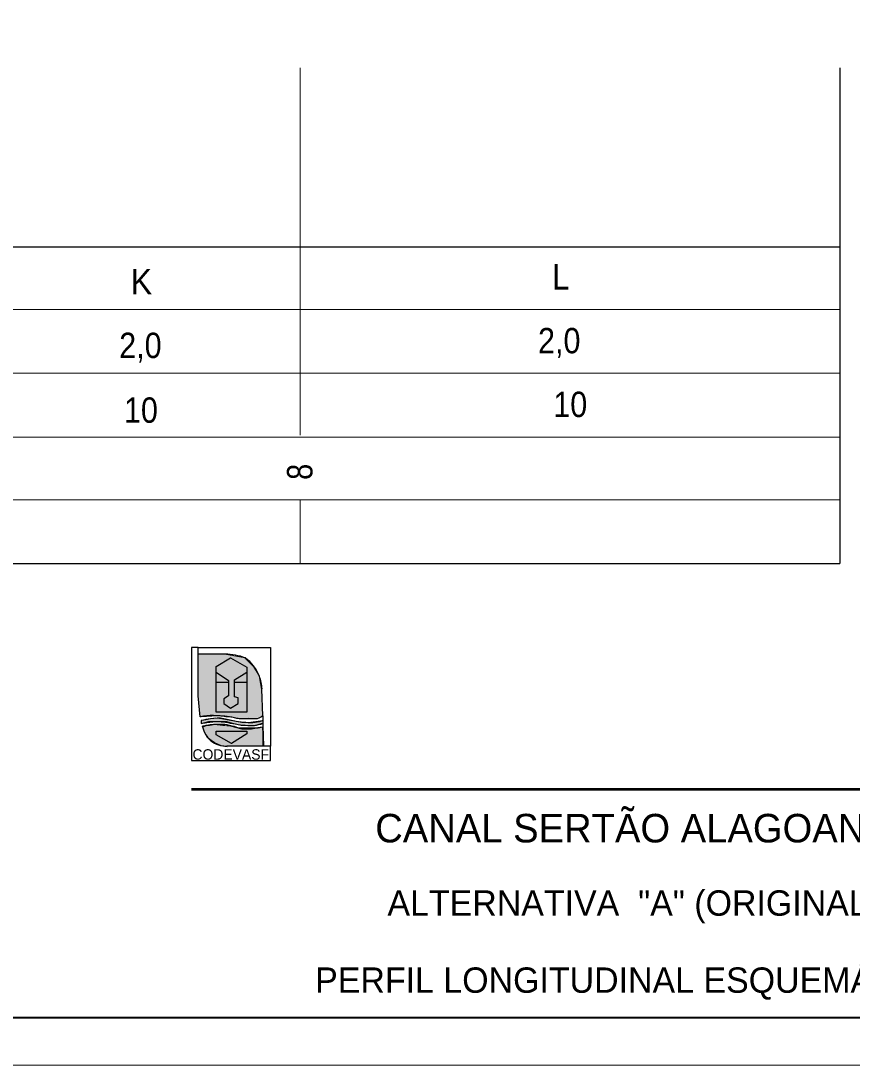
# Model space of a CAD drawing. Extents: x 8426.2 to 8495.4, y 19933.5 to 19963.2.
# Drawn here: x 8482.15 to 8490.88, y 19933.55 to 19944.52 of the extents above; entities that cross this region are included whole.
import ezdxf
from ezdxf.enums import TextEntityAlignment as Align

# ---------------------------------------------------------------- set-up
doc = ezdxf.new("R2010")
doc.units = 0
doc.header["$LTSCALE"] = 0.11
for name, color, linetype, lineweight in [('1', 7, 'Continuous', 35), ('3', 7, 'Continuous', 25), ('8', 7, 'Continuous', 13)]:
    doc.layers.add(name, color=color, linetype=linetype, lineweight=lineweight)

msp = doc.modelspace()

# ---------------------------------------------------------------- hatches: boundary and pattern name
at = {"layer": '8'}
for points in [[(8484.01, 19937.87), (8484.29, 19937.87), (8484.5, 19937.83), (8484.59, 19937.74), (8484.65, 19937.64), (8484.68, 19937.5), (8484.69, 19937.22), (8484.63, 19937.19), (8484.48, 19937.19), (8484.33, 19937.21), (8484.21, 19937.22), (8484.04, 19937.21), (8484.03, 19937.21), (8484.01, 19937.43), (8484.01, 19937.65)], [(8484.04, 19937.17), (8484.04, 19937.14), (8484.12, 19937.16), (8484.26, 19937.16), (8484.31, 19937.16), (8484.42, 19937.13), (8484.52, 19937.12), (8484.6, 19937.12), (8484.69, 19937.14), (8484.69, 19937.17), (8484.54, 19937.15), (8484.47, 19937.15), (8484.26, 19937.19), (8484.19, 19937.2)], [(8484.69, 19936.9), (8484.31, 19936.9), (8484.25, 19936.91), (8484.18, 19936.94), (8484.11, 19936.99), (8484.07, 19937.06), (8484.06, 19937.1), (8484.1, 19937.12), (8484.18, 19937.13), (8484.27, 19937.12), (8484.35, 19937.11), (8484.47, 19937.08), (8484.57, 19937.08), (8484.67, 19937.1), (8484.69, 19937.1)], [(8484.2, 19937.06), (8484.2, 19937.02), (8484.36, 19936.93), (8484.52, 19937.03), (8484.52, 19937.06)]]:
    msp.add_hatch(color=256, dxfattribs=at).paths.add_polyline_path(points)

# ---------------------------------------------------------------- linework, layer by layer
at = {"layer": '1', "lineweight": 53}
msp.add_line((8483.94, 19936.45), (8493.94, 19936.45), dxfattribs=at)
at = {"layer": '1', "lineweight": 13}
msp.add_lwpolyline([(8426.17, 19933.55), (8495.44, 19933.55), (8495.44, 19963.25), (8426.17, 19963.25)], close=True, dxfattribs=at)
at = {"layer": '1', "lineweight": 40}
msp.add_lwpolyline([(8428.67, 19934.05), (8494.94, 19934.05), (8494.94, 19962.75)], dxfattribs=at)
at = {"layer": '3', "lineweight": 13}
for p, q in [((8485.08, 19944.03), (8485.08, 19940.17)), ((8432.23, 19941.49), (8490.75, 19941.49)), ((8432.23, 19940.82), (8490.75, 19940.82)), ((8432.23, 19940.15), (8490.75, 19940.15)), ((8433.47, 19940.15), (8490.75, 19940.15)), ((8432.23, 19939.49), (8490.75, 19939.49)), ((8485.08, 19939.49), (8485.08, 19938.82))]:
    msp.add_line(p, q, dxfattribs=at)
at = {"layer": '3'}
for p, q in [((8490.75, 19944.03), (8490.75, 19938.82)), ((8432.23, 19942.15), (8490.75, 19942.15)), ((8432.23, 19938.82), (8490.75, 19938.82)), ((8484.01, 19937.87), (8484.01, 19937.94)), ((8484.29, 19937.87), (8484.01, 19937.87)), ((8484.2, 19937.26), (8484.2, 19937.74)), ((8484.33, 19937.57), (8484.2, 19937.57)), ((8484.52, 19937.57), (8484.39, 19937.57)), ((8484.69, 19937.22), (8484.68, 19937.5)), ((8484.7, 19936.9), (8484.69, 19937.1)), ((8484.77, 19936.9), (8484.31, 19936.9))]:
    msp.add_line(p, q, dxfattribs=at)
for points in [[(8484.01, 19937.94), (8483.94, 19937.94), (8483.94, 19936.75), (8484.77, 19936.75), (8484.77, 19936.9)], [(8484.01, 19937.94), (8484.77, 19937.94), (8484.77, 19936.9)], [(8484.03, 19937.21), (8484.01, 19937.43), (8484.01, 19937.87)], [(8484.2, 19937.74), (8484.35, 19937.83), (8484.52, 19937.73)], [(8484.52, 19937.73), (8484.52, 19937.26), (8484.2, 19937.26)], [(8484.2, 19937.68), (8484.33, 19937.59), (8484.33, 19937.43), (8484.28, 19937.4), (8484.28, 19937.35), (8484.35, 19937.3), (8484.43, 19937.35), (8484.43, 19937.41), (8484.39, 19937.42), (8484.39, 19937.6), (8484.52, 19937.68)]]:
    msp.add_lwpolyline(points, dxfattribs=at)
msp.add_lwpolyline([(8484.2, 19937.06), (8484.52, 19937.06), (8484.52, 19937.03), (8484.36, 19936.93), (8484.2, 19937.02)], close=True, dxfattribs=at)
msp.add_lwpolyline([(8484.2, 19937.06), (8484.52, 19937.06), (8484.52, 19937.03), (8484.36, 19936.93), (8484.2, 19937.02)], close=True, dxfattribs=at)
for centre, radius, start, end in [((8484.284, 19937.219), 0.649, 70.2011, 89.1197), ((8484.261, 19937.485), 0.421, 21.2511, 54.7896), ((8483.978, 19937.422), 0.709, 6.5558, 17.6915), ((8484.318, 19937.159), 0.267, 191.372, 229.2203), ((8484.323, 19937.205), 0.306, 234.1389, 268.0902)]:
    msp.add_arc(centre, radius, start, end, dxfattribs=at)
for points in [[(8484.69, 19937.22), (8484.63, 19937.19), (8484.56, 19937.19), (8484.51, 19937.19), (8484.44, 19937.19), (8484.34, 19937.21), (8484.24, 19937.22), (8484.1, 19937.22), (8484.03, 19937.21)], [(8484.69, 19937.17), (8484.61, 19937.15), (8484.51, 19937.15), (8484.41, 19937.16), (8484.28, 19937.19), (8484.14, 19937.19), (8484.04, 19937.17)], [(8484.04, 19937.14), (8484.1, 19937.15), (8484.23, 19937.16), (8484.32, 19937.15), (8484.43, 19937.13), (8484.53, 19937.12), (8484.6, 19937.12), (8484.69, 19937.14)], [(8484.69, 19937.1), (8484.58, 19937.09), (8484.48, 19937.09), (8484.45, 19937.09), (8484.34, 19937.12), (8484.24, 19937.13), (8484.1, 19937.12), (8484.06, 19937.11)]]:
    msp.add_spline(points, degree=3, dxfattribs=at)
at = {"layer": '8', "lineweight": 25}
msp.add_line((8484.04, 19937.17), (8484.04, 19937.14), dxfattribs=at)
at = {"layer": '8'}
for points in [[(8483.94, 19936.75), (8483.94, 19937.94), (8484.01, 19937.94), (8484.01, 19937.87), (8484.01, 19937.65), (8484.01, 19937.43), (8484.03, 19937.21), (8484.16, 19937.22), (8484.25, 19937.22), (8484.3, 19937.21), (8484.36, 19937.21), (8484.45, 19937.19), (8484.5, 19937.19), (8484.55, 19937.19), (8484.63, 19937.19), (8484.69, 19937.22), (8484.69, 19937.17), (8484.57, 19937.15), (8484.51, 19937.15), (8484.43, 19937.16), (8484.33, 19937.18), (8484.26, 19937.19), (8484.19, 19937.2), (8484.09, 19937.18), (8484.04, 19937.17), (8484.04, 19937.14), (8484.12, 19937.16), (8484.22, 19937.16), (8484.31, 19937.16), (8484.36, 19937.14), (8484.42, 19937.13), (8484.46, 19937.12), (8484.52, 19937.12), (8484.6, 19937.12), (8484.67, 19937.14), (8484.69, 19937.14), (8484.69, 19937.14), (8484.69, 19937.1), (8484.64, 19937.09), (8484.54, 19937.08), (8484.47, 19937.08), (8484.39, 19937.11), (8484.29, 19937.12), (8484.19, 19937.13), (8484.13, 19937.12), (8484.05, 19937.11), (8484.07, 19937.06), (8484.1, 19937), (8484.15, 19936.96), (8484.19, 19936.93), (8484.24, 19936.91), (8484.3, 19936.9), (8484.37, 19936.9), (8484.54, 19936.9), (8484.77, 19936.9), (8484.77, 19936.75)], [(8484.01, 19937.94), (8484.77, 19937.94), (8484.77, 19936.9), (8484.7, 19936.9), (8484.69, 19937.22), (8484.68, 19937.48), (8484.65, 19937.64), (8484.59, 19937.74), (8484.5, 19937.83), (8484.4, 19937.86), (8484.29, 19937.87), (8484.15, 19937.87), (8484.01, 19937.87)], [(8484.01, 19937.87), (8484.29, 19937.87), (8484.5, 19937.83), (8484.59, 19937.74), (8484.65, 19937.64), (8484.68, 19937.5), (8484.69, 19937.22), (8484.63, 19937.19), (8484.48, 19937.19), (8484.33, 19937.21), (8484.21, 19937.22), (8484.04, 19937.21), (8484.03, 19937.21), (8484.01, 19937.43), (8484.01, 19937.65)], [(8484.04, 19937.17), (8484.04, 19937.14), (8484.12, 19937.16), (8484.26, 19937.16), (8484.31, 19937.16), (8484.42, 19937.13), (8484.52, 19937.12), (8484.6, 19937.12), (8484.69, 19937.14), (8484.69, 19937.17), (8484.54, 19937.15), (8484.47, 19937.15), (8484.26, 19937.19), (8484.19, 19937.2)], [(8484.69, 19936.9), (8484.31, 19936.9), (8484.25, 19936.91), (8484.18, 19936.94), (8484.11, 19936.99), (8484.07, 19937.06), (8484.06, 19937.1), (8484.1, 19937.12), (8484.18, 19937.13), (8484.27, 19937.12), (8484.35, 19937.11), (8484.47, 19937.08), (8484.57, 19937.08), (8484.67, 19937.1), (8484.69, 19937.1)], [(8484.2, 19937.06), (8484.2, 19937.02), (8484.36, 19936.93), (8484.52, 19937.03), (8484.52, 19937.06)]]:
    msp.add_lwpolyline(points, close=True, dxfattribs=at)
for points in [[(8484.52, 19937.73), (8484.35, 19937.83), (8484.2, 19937.74), (8484.2, 19937.26)], [(8484.2, 19937.26), (8484.52, 19937.26), (8484.52, 19937.73)]]:
    msp.add_lwpolyline(points, dxfattribs=at)
at = {"layer": '8', "lineweight": 25}
msp.add_lwpolyline([(8484.69, 19937.22), (8484.69, 19937.17), (8484.69, 19937.14), (8484.69, 19937.1)], dxfattribs=at)

# ---------------------------------------------------------------- texts
at = {"layer": '1'}
for s, height, p in [('CANAL SERTÃO ALAGOANO', 0.2999, (8488.6, 19935.89)), ('ALTERNATIVA  "A" (ORIGINAL)', 0.2665, (8488.58, 19935.12)), ('PERFIL LONGITUDINAL ESQUEMÁTICO', 0.2665, (8488.595, 19934.31))]:
    msp.add_text(s, height=height, dxfattribs=at).set_placement(p, align=Align.CENTER)
at = {"layer": '3'}
for s, height, width, p in [('K', 0.267, 0.95, (8483.3, 19941.65)), ('L', 0.267, 0.9, (8487.73, 19941.7)), ('2,0', 0.2665, 0.9, (8483.18, 19940.98)), ('2,0', 0.2665, 0.9, (8487.58, 19941.03)), ('10', 0.2665, 0.9, (8487.74, 19940.36)), ('10', 0.2665, 0.9, (8483.23, 19940.3))]:
    msp.add_text(s, height=height, dxfattribs=dict(at, width=width)).set_placement(p)
at = {"layer": '3', "width": 0.85}
msp.add_text('8', height=0.267, rotation=90, dxfattribs=at).set_placement((8485.21, 19939.7))
at = {"layer": '3'}
msp.add_text('CODEVASF', height=0.1093, dxfattribs=at).set_placement((8483.95, 19936.76))

doc.saveas('drawing.dxf')
